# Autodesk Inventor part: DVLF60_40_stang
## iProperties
Created: 2010-03
Part Number: DVLF60_40_stang
Document SubType Name: Modeling
Designer: TB
Mass: 362.535 g
Surface Area: 383.144 cm^2
Volume: 362.535 cm^3
Density: 1 g/cm^3
Author: TB
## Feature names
1. Revolution1
2. Fillet1
3. Revolution2
